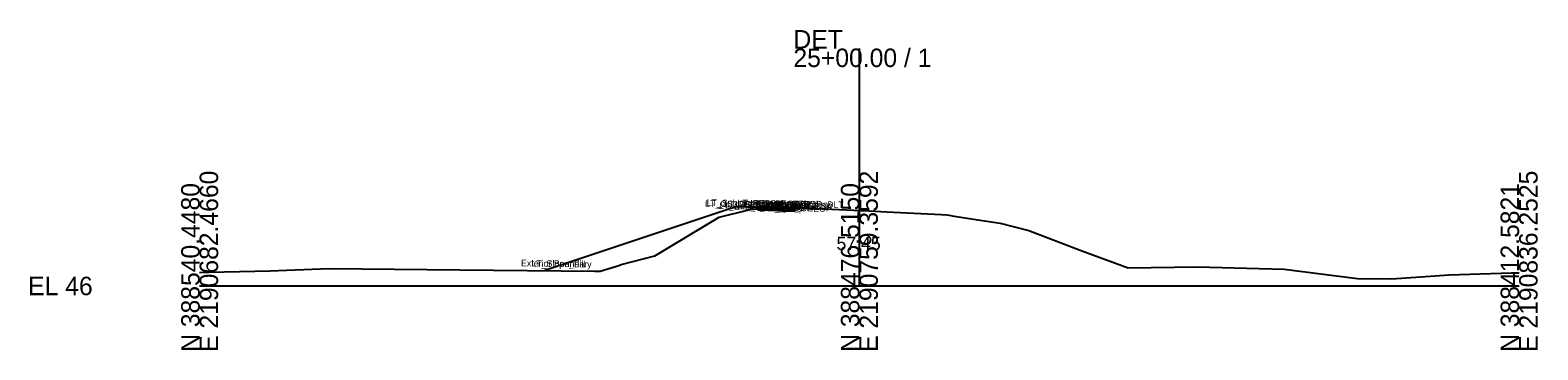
# Model space of a CAD drawing. Extents: x -26 to 1203, y -10 to 9543.
# Drawn here: x 974.3 to 1202.8, y 4990.3 to 5038.8 of the extents above; entities that cross this region are included whole.
import ezdxf

# ---------------------------------------------------------------- set-up
doc = ezdxf.new("R2010")
doc.units = 0
for name, color, linetype in [('Default', 7, 'Continuous'), ('Exist Cross Section Cell', 7, 'Continuous'), ('Exist XS Center Line Elevation Label', 7, 'Continuous'), ('Exist XS Ground Line', 7, 'Continuous'), ('Prop CMT Pvmt Course 1', 7, 'Continuous'), ('Prop CMT Pvmt Course 2', 7, 'Continuous'), ('Prop CMT Pvmt Surface', 7, 'Continuous'), ('Prop CMT Pvmt Surface Shoulder', 7, 'Continuous'), ('Prop CMT Shld Paved Course 1', 7, 'Continuous'), ('Prop CMT Shld Paved Course 2', 7, 'Continuous'), ('Prop CMT Slope Grass', 7, 'Continuous'), ('Prop CMT Subgrade Earthwork', 7, 'Continuous'), ('Scratch_Level_0', 7, 'Continuous')]:
    doc.layers.add(name, color=color, linetype=linetype)

msp = doc.modelspace()

# ---------------------------------------------------------------- linework, layer by layer
at = {"layer": 'Exist Cross Section Cell'}
for p, q in [((1100, 5000), (1100, 5036)), ((1000, 5000), (1100, 5000)), ((1100, 5000), (1200, 5000))]:
    msp.add_line(p, q, dxfattribs=at)
at = {"layer": 'Exist XS Ground Line'}
for p, q in [((1083.95, 5011.66), (1088.09, 5011.97)), ((1088.09, 5011.97), (1088.69, 5012)), ((1088.69, 5012), (1090.22, 5011.94)), ((1090.22, 5011.94), (1090.77, 5011.92)), ((1090.77, 5011.92), (1093.65, 5011.77)), ((1093.65, 5011.77), (1100.23, 5011.44)), ((1068.97, 5004.57), (1078.75, 5010.41)), ((1078.75, 5010.41), (1083.26, 5011.54)), ((1083.26, 5011.54), (1083.63, 5011.64)), ((1083.63, 5011.64), (1083.95, 5011.66)), ((1100.23, 5011.44), (1101.44, 5011.38)), ((1101.44, 5011.38), (1104.14, 5011.25)), ((1104.14, 5011.25), (1112.41, 5010.84)), ((1112.41, 5010.84), (1113.23, 5010.77)), ((1113.23, 5010.77), (1113.63, 5010.72)), ((1113.63, 5010.72), (1114.04, 5010.62)), ((1114.04, 5010.62), (1117.3, 5010.14)), ((1117.3, 5010.14), (1121.34, 5009.52)), ((1121.34, 5009.52), (1123.1, 5009.07)), ((1123.1, 5009.07), (1125.7, 5008.43)), ((1125.7, 5008.43), (1133.48, 5005.45)), ((1133.48, 5005.45), (1140.73, 5002.73)), ((1010.71, 5002.29), (1019.59, 5002.65)), ((1019.59, 5002.65), (1039.45, 5002.45)), ((1060.7, 5002.22), (1063.54, 5003.11)), ((1063.54, 5003.11), (1063.87, 5003.23)), ((1063.87, 5003.23), (1068.97, 5004.57)), ((1140.73, 5002.73), (1151.19, 5002.88)), ((1151.19, 5002.88), (1164.38, 5002.53)), ((1000, 5002.06), (1001.41, 5002.07)), ((1001.41, 5002.07), (1010.71, 5002.29)), ((1039.45, 5002.45), (1059.91, 5002.23)), ((1059.91, 5002.23), (1060.7, 5002.22)), ((1164.38, 5002.53), (1175.51, 5001.14)), ((1175.51, 5001.14), (1180.72, 5001.06)), ((1180.72, 5001.06), (1189.4, 5001.68)), ((1189.4, 5001.68), (1198.85, 5002)), ((1198.85, 5002), (1200, 5002))]:
    msp.add_line(p, q, dxfattribs=at)
at = {"layer": 'Prop CMT Pvmt Course 1'}
for points in [[(1090.22, 5011.84), (1087.59, 5011.94)], [(1087.59, 5011.94), (1087.59, 5011.69)], [(1090.22, 5011.59), (1090.22, 5011.84)], [(1087.59, 5011.69), (1090.22, 5011.59)]]:
    msp.add_lwpolyline(points, dxfattribs=at)
at = {"layer": 'Prop CMT Pvmt Course 2'}
for points in [[(1090.22, 5011.59), (1087.59, 5011.69)], [(1087.59, 5011.69), (1087.59, 5011.44)], [(1087.59, 5011.44), (1090.22, 5011.34)], [(1090.22, 5011.34), (1090.22, 5011.59)]]:
    msp.add_lwpolyline(points, dxfattribs=at)
at = {"layer": 'Prop CMT Pvmt Surface'}
msp.add_lwpolyline([(1090.22, 5011.84), (1087.59, 5011.94)], dxfattribs=at)
at = {"layer": 'Prop CMT Pvmt Surface Shoulder'}
msp.add_lwpolyline([(1087.59, 5011.94), (1085.6, 5012.02)], dxfattribs=at)
at = {"layer": 'Prop CMT Shld Paved Course 1'}
for points in [[(1087.59, 5011.94), (1085.6, 5012.02), (1085.36, 5011.78)], [(1085.36, 5011.78), (1087.59, 5011.69)], [(1087.59, 5011.69), (1087.59, 5011.94)]]:
    msp.add_lwpolyline(points, dxfattribs=at)
at = {"layer": 'Prop CMT Shld Paved Course 2'}
for points in [[(1087.59, 5011.69), (1085.36, 5011.78), (1084.86, 5011.8), (1084.62, 5011.56)], [(1084.62, 5011.56), (1087.59, 5011.44)], [(1087.59, 5011.44), (1087.59, 5011.69)]]:
    msp.add_lwpolyline(points, dxfattribs=at)
at = {"layer": 'Prop CMT Slope Grass'}
for points in [[(1081.13, 5011.93), (1052.34, 5002.32)], [(1085.6, 5012.02), (1081.13, 5011.93)]]:
    msp.add_lwpolyline(points, dxfattribs=at)
at = {"layer": 'Prop CMT Subgrade Earthwork'}
for points in [[(1084.62, 5011.56), (1084.19, 5012)], [(1087.59, 5011.44), (1090.22, 5011.34), (1090.23, 5011.94)], [(1087.59, 5011.44), (1084.62, 5011.56)]]:
    msp.add_lwpolyline(points, dxfattribs=at)

# ---------------------------------------------------------------- texts
at = {"layer": 'Default'}
msp.add_text('-', height=0.0001, dxfattribs=at).set_placement((1000, 5000))
at = {"layer": 'Exist Cross Section Cell'}
for s, p in [('DET', (1090, 5036)), ('25+00.00 / 1', (1090, 5033.2)), ('EL 46', (974, 4998.6))]:
    msp.add_text(s, height=2.8, dxfattribs=at).set_placement(p)
for s, p in [('E 2190682.4660', (1002.8, 4990)), ('E 2190759.3592', (1102.8, 4990)), ('E 2190836.2525', (1202.8, 4990)), ('N 388540.4480', (1000, 4990)), ('N 388476.5150', (1100, 4990)), ('N 388412.5821', (1200, 4990))]:
    msp.add_text(s, height=2.8, rotation=90, dxfattribs=at).set_placement(p)
at = {"layer": 'Exist XS Center Line Elevation Label'}
msp.add_text('57.45', height=2, dxfattribs=at).set_placement((1096.53, 5005.45))
at = {"layer": 'Scratch_Level_0'}
for s, p in [('LT_GS_OS_CTL', (1076.6, 5012.02)), ('LT_Sub_Trench_Out_DLT', (1076.84, 5012.14)), ('LT_Sub_Trench_Out', (1078.73, 5011.68)), ('LT_PS2_Shelf_Out', (1079.52, 5011.91)), ('LT_PS2_OEOP', (1081.14, 5011.87)), ('LT_PS1_OEOP', (1081.5, 5012.1)), ('LT_PV2_OEOT', (1083.34, 5011.78)), ('LT_Sub_OEOT', (1083.36, 5011.53)), ('LT_PV1_OEOT', (1083.46, 5012.02)), ('LT_Sub_OEEOP_DLT', (1084.18, 5012.06)), ('Exterior Boundary', (1084.89, 5012.05)), ('LT_PV2_OEEOP', (1085.61, 5011.68)), ('LT_Sub_OEEOP', (1085.63, 5011.43)), ('PV1_PGL', (1087.69, 5011.89)), ('Exterior Boundary', (1048.7, 5002.99)), ('LT_Slope_Fill', (1050.27, 5002.96))]:
    msp.add_text(s, height=1, rotation=358.8836, dxfattribs=at).set_placement(p)

doc.saveas('drawing.dxf')
